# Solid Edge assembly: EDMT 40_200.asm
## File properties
Title: Zylinder
Author: bmolnar
Template: iso metric assembly.asm
Last saved by: bmolnar
Revision: 14
Application: Solid Edge
Username: bmolnar
Dokumentum tartalom típus: 1
Document Number: EDMT 40/200
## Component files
Platte.par
use.par
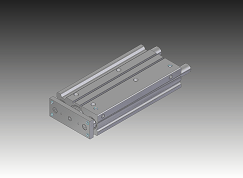
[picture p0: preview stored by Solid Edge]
